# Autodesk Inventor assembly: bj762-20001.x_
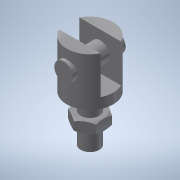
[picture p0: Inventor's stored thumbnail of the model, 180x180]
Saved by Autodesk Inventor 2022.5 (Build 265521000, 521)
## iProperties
Part Number: bj762-20001.x_
Material: 一般
Document SubType Name: Assembly
Designer: ImaoCorp
Sending System: SOLIDWORKS 2017-2017317
MC: AMD64
MC_MODEL: Intel64 Family 6 Model 60 Stepping 3, GenuineIntel
OS: Windows_NT
FRU: Parasolid Version 29.0, build 201,  4-17-2017
FORMAT: text
GUISE: transmit
KEY: bj762-20001
FILE: bj762-20001.x_t
DATE: Fri Mar 15 10:09:21 2019
Author: ImaoCorp
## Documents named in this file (3)
- X:\14_SW2022-Inv2022\00_全2023-1023新製品(TCC)まで\b\bj762-20001\BJ762-20001.iam
- X:\14_SW2022-Inv2022\00_全2023-1023新製品(TCC)まで\b\bj762-20001\bj762-20001_01.ipt
- X:\14_SW2022-Inv2022\00_全2023-1023新製品(TCC)まで\b\bj762-20001\bj762-20001_02.ipt
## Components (2 placed, 2 different names)
1. bj762-20001_01
2. bj762-20001_02
